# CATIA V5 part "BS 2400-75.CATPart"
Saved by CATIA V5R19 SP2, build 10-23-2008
Part number: BS 2400-75
Bounding box of the stored display mesh (mm): x -37.351 to 37.351, y -37.351 to 37.351, z 0 to 195
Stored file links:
  C:\Users\Bora\Desktop\3D Katı model\BS serisi\BS 2400\BS 2400-75.CATPart
  C:\Program Files\Dassault Systemes\B19\intel_a\reffiles\standard\MetricThickPitch.txt
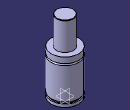
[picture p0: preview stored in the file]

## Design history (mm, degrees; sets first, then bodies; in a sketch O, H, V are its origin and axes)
Body1 (main body)
  Sketch1 on yz-plane, origin (0, 0, 0), H (0, 1, 0), V (0, 0, 1)
    point P1 (22.5, 194)
    point P3 (22.5, 194)
    point P7 (37.5, 103.5)
    point P9 (37.5, 103.5)
    point P10 (37.5, 98.5)
    point P14 (37.5, 98.5)
    line L1 (22.5, 194) -> (22.5, 119)
    arc A1 centre (21.5, 194) radius 1 from (22.5, 194) to (21.5, 195) ccw
    line L2 (37.5, 0) -> (37.5, 8)
    line L3 (37.5, 103.5) -> (37.5, 119)
    arc A2 centre (37.5, 101) radius 2.5 from (37.5, 103.5) to (37.5, 98.5) ccw
    line L4 (34.5, 13) -> (34.5, 8)
    line L5 (37.5, 13) -> (37.5, 98.5)
    line L6 (21.5, 195) -> (0, 195)
    point P15 (0, 195)
    line L7 (22.5, 119) -> (37.5, 119)
    line L8 (0, 0) -> (37.5, 0)
    line L9 (34.5, 13) -> (37.5, 13)
    line L10 (34.5, 8) -> (37.5, 8)
    coincidence: P15 V, P1 P3, P7 P9, P10 P14
    tangency: L6 A1
    horizontal: L7 H, L8 H, L9 H, L10 H
  Shaft1: profile Sketch1, axis Sketch1.V, angle 360
  Sketch2 on face of Shaft1 from Sketch1.L8, origin (0, 0, 0), H (1, 0, 0), V (0, -1, 0)
    point P1 (20, 0)
    distance P1 V = 20
  Hole1: placed by Sketch2, at (20, 0, 0) direction (0, 0, 1), diameter 6.647, depth 5, threaded "M8", thread diameter 8, thread depth 5, pitch 1.25
  CircPattern1: of Hole1, instances 4, angular step 90, axis from xy-plane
